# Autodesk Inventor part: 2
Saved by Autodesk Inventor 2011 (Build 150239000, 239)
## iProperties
Created: 2012-07
Part Number: 2
Document SubType Name: Modeling
Designer: R.JANSSEN
Mass: 1072.6 g
Surface Area: 1179.1 cm^2
Volume: 1072.6 cm^3
Density: 1 g/cm^3
Author: R.JANSSEN
Translation Standard: STEP AP203
FileName: //expscmdclustefs.cadenas.external/client_exchange/iodir/jobs/output/wkb47459197_no0//0//151580_DNG_6_12_PPV_A_2_03.stp
PostProcessor: Build: 239, Release: 2011 RTM - Date: Wed 02/17/2010
Sent Units: millimeter
Uncertainty: 0.0
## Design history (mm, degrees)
feature "Base1"
node "2"
